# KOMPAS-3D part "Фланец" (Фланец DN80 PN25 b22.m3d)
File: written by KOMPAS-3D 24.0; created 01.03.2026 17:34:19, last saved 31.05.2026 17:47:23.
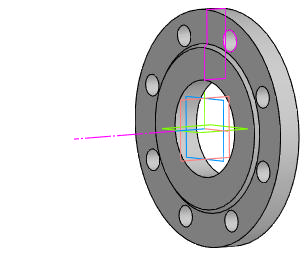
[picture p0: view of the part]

Document properties: Автор: R2D2; Полное имя файла: E:\Работа\Зайцев\GVWR2121M-2W-F-ОСТ Задвижка клиновая 30с964нж DN.ru Ду50-300 Ру25\исходные материалы\DN80\Фланец DN80 PN25 b20.m3d

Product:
- Part/product: Фланец
    Масса: 3.627543
    additional columns: Типовые

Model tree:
1. Эскиз:2
2. Элемент вращения:1
     Угол 1 = 360
3. Эскиз:3  (with: Грань.Элемент вращения:1)
4. Элемент выдавливания:2
     Расстояние 2 = 19
5. Массив по концентрической сетке:1  (with: Элемент выдавливания:2, Эскиз:3, Грань.Элемент вращения:1)  (8 pattern instances)
     Шаг 2 = 360
6. Эскиз:4  (with: Грань.Элемент вращения:1)
7. Элемент выдавливания:3
     Расстояние 2 = 2.5

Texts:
  Линейный размер с обрывом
